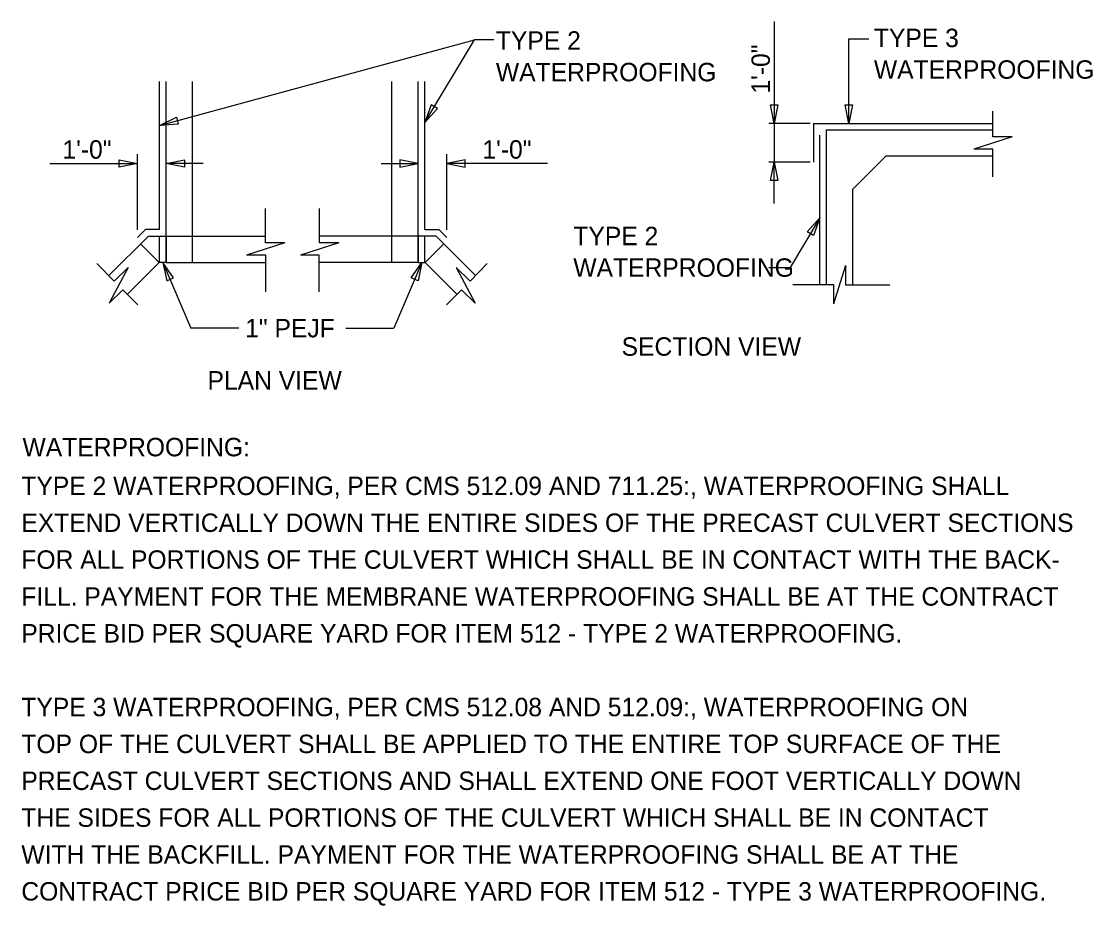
# Model space of a CAD drawing. Extents: x -1609 to 1184, y -412 to 394.
# Drawn here: x 637.72 to 653.99, y 282.57 to 296 of the extents above; entities that cross this region are included whole.
import ezdxf

# ---------------------------------------------------------------- set-up
doc = ezdxf.new("R2010")
doc.units = 0
for name, color, linetype in [('SH_Data', 7, 'Continuous'), ('ST_Details', 7, 'Continuous'), ('ST_Text', 7, 'Continuous')]:
    doc.layers.add(name, color=color, linetype=linetype)

msp = doc.modelspace()

# ---------------------------------------------------------------- linework, layer by layer
at = {"layer": 'ST_Details'}
for p, q in [((639.823, 292.84), (639.823, 295.089)), ((639.923, 292.339), (639.923, 295.089)), ((640.323, 292.339), (640.323, 295.089)), ((643.349, 292.339), (643.349, 295.089)), ((643.749, 292.339), (643.749, 295.089)), ((643.849, 292.84), (643.849, 295.089)), ((652.473, 294.246), (652.473, 294.638)), ((649.754, 294.451), (649.754, 293.863)), ((649.754, 294.451), (652.474, 294.451)), ((649.849, 292.002), (649.849, 294.274)), ((649.949, 292.002), (649.949, 294.354)), ((649.949, 294.354), (652.474, 294.354)), ((652.767, 294.246), (652.187, 294.062)), ((652.767, 294.246), (652.473, 294.246)), ((650.849, 293.954), (650.349, 293.454)), ((652.478, 293.954), (650.849, 293.954)), ((652.477, 294.062), (652.187, 294.062)), ((652.477, 293.642), (652.477, 294.062)), ((650.349, 291.999), (650.349, 293.454)), ((641.431, 292.635), (641.431, 293.16)), ((642.25, 292.635), (642.25, 293.16)), ((639.61, 292.84), (639.487, 292.717)), ((639.823, 292.84), (639.61, 292.84)), ((643.849, 292.84), (644.061, 292.84)), ((644.061, 292.84), (644.184, 292.717)), ((639.652, 292.74), (639.051, 292.139)), ((639.534, 292.622), (639.816, 292.339)), ((639.652, 292.74), (641.431, 292.74)), ((641.725, 292.635), (641.144, 292.451)), ((641.725, 292.635), (641.431, 292.635)), ((642.544, 292.635), (641.964, 292.451)), ((644.02, 292.74), (642.25, 292.74)), ((642.544, 292.635), (642.25, 292.635)), ((644.138, 292.622), (643.855, 292.339)), ((644.02, 292.74), (644.621, 292.139)), ((641.434, 292.451), (641.144, 292.451)), ((641.434, 291.894), (641.434, 292.451)), ((642.247, 292.451), (641.964, 292.451)), ((642.247, 291.894), (642.247, 292.451)), ((639.134, 292.054), (638.872, 292.321)), ((639.816, 292.339), (639.333, 291.856)), ((639.923, 292.339), (639.816, 292.339)), ((639.923, 292.339), (641.434, 292.339)), ((643.749, 292.339), (642.247, 292.339)), ((643.749, 292.339), (643.855, 292.339)), ((643.855, 292.339), (644.338, 291.856)), ((644.537, 292.054), (644.799, 292.321)), ((650.24, 292.293), (650.056, 291.712)), ((650.24, 292.293), (650.24, 291.999)), ((639.344, 292.26), (639.058, 291.722)), ((639.344, 292.26), (639.134, 292.054)), ((644.327, 292.26), (644.613, 291.722)), ((644.327, 292.26), (644.537, 292.054)), ((649.44, 292.002), (650.056, 292.002)), ((650.056, 292.002), (650.056, 291.712)), ((650.24, 291.999), (650.91, 291.999)), ((639.266, 291.925), (639.058, 291.722)), ((639.49, 291.696), (639.266, 291.925)), ((644.181, 291.696), (644.405, 291.925)), ((644.405, 291.925), (644.613, 291.722))]:
    msp.add_line(p, q, dxfattribs=at)
for points in [[(639.82, 292.74), (639.923, 292.74), (639.923, 292.339), (639.82, 292.339)], [(639.82, 292.74), (639.923, 292.74), (639.923, 292.339), (639.82, 292.339)], [(643.851, 292.74), (643.749, 292.74), (643.749, 292.339), (643.851, 292.339)], [(643.851, 292.74), (643.749, 292.74), (643.749, 292.339), (643.851, 292.339)]]:
    msp.add_lwpolyline(points, close=True, dxfattribs=at)
at = {"layer": 'ST_Text'}
for p, q in [((649.155, 296.001), (649.155, 294.451)), ((639.823, 294.419), (644.606, 295.722)), ((643.849, 294.465), (644.606, 295.722)), ((644.9, 295.722), (644.606, 295.722)), ((650.288, 295.738), (650.594, 295.738)), ((650.288, 294.451), (650.288, 295.738)), ((649.702, 294.451), (649.076, 294.451)), ((649.155, 294.451), (649.155, 293.863)), ((639.487, 292.835), (639.487, 293.984)), ((644.184, 292.835), (644.184, 293.984)), ((638.156, 293.844), (639.487, 293.844)), ((640.483, 293.844), (639.923, 293.844)), ((643.189, 293.844), (643.749, 293.844)), ((645.715, 293.844), (644.184, 293.844)), ((649.702, 293.863), (649.076, 293.863)), ((649.155, 293.236), (649.155, 293.863)), ((649.849, 293.015), (649.399, 292.264)), ((639.873, 292.339), (640.298, 291.339)), ((643.806, 292.339), (643.381, 291.339)), ((649.074, 292.264), (649.399, 292.264)), ((641.027, 291.339), (640.298, 291.339)), ((642.651, 291.339), (643.381, 291.339))]:
    msp.add_line(p, q, dxfattribs=at)
for points in [[(643.945, 294.734), (643.849, 294.465), (644.041, 294.676)], [(649.211, 294.731), (649.155, 294.451), (649.099, 294.731)], [(650.344, 294.731), (650.288, 294.451), (650.232, 294.731)], [(640.107, 294.438), (639.823, 294.419), (640.078, 294.547)], [(639.207, 293.9), (639.487, 293.844), (639.207, 293.788)], [(640.203, 293.788), (639.923, 293.844), (640.203, 293.9)], [(643.469, 293.788), (643.749, 293.844), (643.469, 293.9)], [(644.464, 293.9), (644.184, 293.844), (644.464, 293.788)], [(649.099, 293.583), (649.155, 293.863), (649.211, 293.583)], [(649.657, 292.803), (649.849, 293.015), (649.753, 292.746)], [(640.034, 292.103), (639.873, 292.339), (639.931, 292.059)], [(643.645, 292.103), (643.806, 292.339), (643.748, 292.06)]]:
    msp.add_lwpolyline(points, close=True, dxfattribs=at)

# ---------------------------------------------------------------- texts
at = {"layer": 'SH_Data'}
for s, p in [('TYPE 3', (650.669, 295.61)), ('TYPE 2', (644.929, 295.571)), ('WATERPROOFING', (650.669, 295.13)), ('WATERPROOFING', (644.929, 295.091)), ('1\'-0"', (638.347, 293.916)), ('1\'-0"', (644.724, 293.916)), ('TYPE 2', (646.105, 292.601)), ('WATERPROOFING', (646.105, 292.121)), ('1" PEJF', (641.122, 291.201)), ('SECTION VIEW', (646.838, 290.922)), ('PLAN VIEW', (640.55, 290.408)), ('WATERPROOFING:', (637.741, 289.394)), ('TYPE 2 WATERPROOFING, PER CMS 512.09 AND 711.25:, WATERPROOFING SHALL', (637.723, 288.805)), ('EXTEND VERTICALLY DOWN THE ENTIRE SIDES OF THE PRECAST CULVERT SECTIONS', (637.723, 288.245)), ('FOR ALL PORTIONS OF THE CULVERT WHICH SHALL BE IN CONTACT WITH THE BACK-', (637.723, 287.685)), ('FILL. PAYMENT FOR THE MEMBRANE WATERPROOFING SHALL BE AT THE CONTRACT', (637.723, 287.125)), ('PRICE BID PER SQUARE YARD FOR ITEM 512 - TYPE 2 WATERPROOFING.', (637.723, 286.565)), ('TYPE 3 WATERPROOFING, PER CMS 512.08 AND 512.09:, WATERPROOFING ON', (637.723, 285.445)), ('TOP OF THE CULVERT SHALL BE APPLIED TO THE ENTIRE TOP SURFACE OF THE', (637.723, 284.885)), ('PRECAST CULVERT SECTIONS AND SHALL EXTEND ONE FOOT VERTICALLY DOWN', (637.723, 284.325)), ('THE SIDES FOR ALL PORTIONS OF THE CULVERT WHICH SHALL BE IN CONTACT', (637.723, 283.765)), ('WITH THE BACKFILL. PAYMENT FOR THE WATERPROOFING SHALL BE AT THE', (637.723, 283.205)), ('CONTRACT PRICE BID PER SQUARE YARD FOR ITEM 512 - TYPE 3 WATERPROOFING.', (637.723, 282.645))]:
    msp.add_text(s, height=0.28, dxfattribs=at).set_placement(p)
msp.add_text('1\'-0"', height=0.28, rotation=90, dxfattribs=at).set_placement((649.09, 294.904))

doc.saveas('drawing.dxf')
